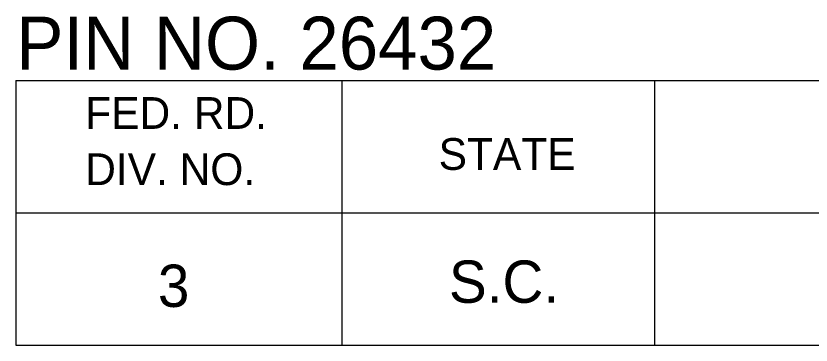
# Model space of a CAD drawing. Extents: x 1000 to 1162, y 999 to 8520.
# Drawn here: x 1133.06 to 1140.57, y 6160.05 to 6163.16 of the extents above; entities that cross this region are included whole.
import ezdxf

# ---------------------------------------------------------------- set-up
doc = ezdxf.new("R2010")
doc.units = 0
doc.layers.add('Level 20', color=7, linetype='Continuous')
doc.layers.add('Level 3', color=7, linetype='Continuous')

msp = doc.modelspace()

# ---------------------------------------------------------------- linework, layer by layer
at = {"layer": 'Level 3'}
for p, q in [((1133.055, 6162.5458), (1161.555, 6162.5458)), ((1133.055, 6162.5458), (1133.055, 6160.0458)), ((1133.055, 6162.5458), (1161.555, 6162.5458)), ((1133.055, 6162.5458), (1133.055, 6160.0458)), ((1133.055, 6162.5458), (1161.555, 6162.5458)), ((1133.055, 6162.5458), (1133.055, 6160.0458)), ((1133.055, 6162.5458), (1161.555, 6162.5458)), ((1133.055, 6162.5458), (1133.055, 6160.0458)), ((1133.055, 6162.5458), (1161.555, 6162.5458)), ((1133.055, 6162.5458), (1133.055, 6160.0458)), ((1133.055, 6162.5458), (1161.555, 6162.5458)), ((1133.055, 6162.5458), (1133.055, 6160.0458)), ((1133.055, 6162.5458), (1161.555, 6162.5458)), ((1133.055, 6162.5458), (1133.055, 6160.0458)), ((1133.055, 6162.5458), (1161.555, 6162.5458)), ((1133.055, 6162.5458), (1133.055, 6160.0458)), ((1133.055, 6162.5458), (1161.555, 6162.5458)), ((1133.055, 6162.5458), (1133.055, 6160.0458)), ((1133.055, 6162.5458), (1161.555, 6162.5458)), ((1133.055, 6162.5458), (1133.055, 6160.0458)), ((1133.055, 6162.5458), (1161.555, 6162.5458)), ((1133.055, 6162.5458), (1133.055, 6160.0458)), ((1133.055, 6162.5458), (1161.555, 6162.5458)), ((1133.055, 6162.5458), (1133.055, 6160.0458)), ((1133.055, 6162.5458), (1161.555, 6162.5458)), ((1133.055, 6162.5458), (1133.055, 6160.0458)), ((1133.055, 6162.5458), (1161.555, 6162.5458)), ((1133.055, 6162.5458), (1133.055, 6160.0458)), ((1133.055, 6162.5458), (1161.555, 6162.5458)), ((1133.055, 6162.5458), (1133.055, 6160.0458)), ((1133.055, 6162.5458), (1161.555, 6162.5458)), ((1133.055, 6162.5458), (1133.055, 6160.0458)), ((1133.055, 6162.5458), (1161.555, 6162.5458)), ((1133.055, 6162.5458), (1133.055, 6160.0458)), ((1133.055, 6162.5458), (1161.555, 6162.5458)), ((1133.055, 6162.5458), (1133.055, 6160.0458)), ((1133.055, 6162.5458), (1161.555, 6162.5458)), ((1133.055, 6162.5458), (1133.055, 6160.0458)), ((1133.055, 6162.5458), (1161.555, 6162.5458)), ((1133.055, 6162.5458), (1133.055, 6160.0458)), ((1133.055, 6162.5458), (1161.555, 6162.5458)), ((1133.055, 6162.5458), (1133.055, 6160.0458)), ((1133.055, 6162.5458), (1161.555, 6162.5458)), ((1133.055, 6162.5458), (1133.055, 6160.0458)), ((1133.055, 6162.5458), (1161.555, 6162.5458)), ((1133.055, 6162.5458), (1133.055, 6160.0458)), ((1133.055, 6162.5458), (1161.555, 6162.5458)), ((1133.055, 6162.5458), (1133.055, 6160.0458)), ((1133.055, 6162.5458), (1161.555, 6162.5458)), ((1133.055, 6162.5458), (1133.055, 6160.0458)), ((1133.055, 6162.5458), (1161.555, 6162.5458)), ((1133.055, 6162.5458), (1133.055, 6160.0458)), ((1133.055, 6162.5458), (1161.555, 6162.5458)), ((1133.055, 6162.5458), (1133.055, 6160.0458)), ((1133.055, 6162.5458), (1161.555, 6162.5458)), ((1133.055, 6162.5458), (1133.055, 6160.0458)), ((1133.055, 6162.5458), (1161.555, 6162.5458)), ((1133.055, 6162.5458), (1133.055, 6160.0458)), ((1133.055, 6162.5458), (1161.555, 6162.5458)), ((1133.055, 6162.5458), (1133.055, 6160.0458)), ((1133.055, 6162.5458), (1161.555, 6162.5458)), ((1133.055, 6162.5458), (1133.055, 6160.0458)), ((1133.055, 6162.5458), (1161.555, 6162.5458)), ((1133.055, 6162.5458), (1133.055, 6160.0458)), ((1133.055, 6162.5458), (1161.555, 6162.5458)), ((1133.055, 6162.5458), (1133.055, 6160.0458)), ((1133.055, 6162.5458), (1161.555, 6162.5458)), ((1133.055, 6162.5458), (1133.055, 6160.0458)), ((1133.055, 6162.5458), (1161.555, 6162.5458)), ((1133.055, 6162.5458), (1133.055, 6160.0458)), ((1133.055, 6162.5458), (1161.555, 6162.5458)), ((1133.055, 6162.5458), (1133.055, 6160.0458)), ((1133.055, 6162.5458), (1161.555, 6162.5458)), ((1133.055, 6162.5458), (1133.055, 6160.0458)), ((1133.055, 6162.5458), (1161.555, 6162.5458)), ((1133.055, 6162.5458), (1133.055, 6160.0458)), ((1133.055, 6162.5458), (1161.555, 6162.5458)), ((1133.055, 6162.5458), (1133.055, 6160.0458)), ((1133.055, 6162.5458), (1161.555, 6162.5458)), ((1133.055, 6162.5458), (1133.055, 6160.0458)), ((1133.055, 6162.5458), (1161.555, 6162.5458)), ((1133.055, 6162.5458), (1133.055, 6160.0458)), ((1133.055, 6162.5458), (1161.555, 6162.5458)), ((1133.055, 6162.5458), (1133.055, 6160.0458)), ((1133.055, 6162.5458), (1161.555, 6162.5458)), ((1133.055, 6162.5458), (1133.055, 6160.0458)), ((1136.1323, 6162.5458), (1136.1323, 6160.0458)), ((1136.1323, 6162.5458), (1136.1323, 6160.0458)), ((1136.1323, 6162.5458), (1136.1323, 6160.0458)), ((1136.1323, 6162.5458), (1136.1323, 6160.0458)), ((1136.1323, 6162.5458), (1136.1323, 6160.0458)), ((1136.1323, 6162.5458), (1136.1323, 6160.0458)), ((1136.1323, 6162.5458), (1136.1323, 6160.0458)), ((1136.1323, 6162.5458), (1136.1323, 6160.0458)), ((1136.1323, 6162.5458), (1136.1323, 6160.0458)), ((1136.1323, 6162.5458), (1136.1323, 6160.0458)), ((1136.1323, 6162.5458), (1136.1323, 6160.0458)), ((1136.1323, 6162.5458), (1136.1323, 6160.0458)), ((1136.1323, 6162.5458), (1136.1323, 6160.0458)), ((1136.1323, 6162.5458), (1136.1323, 6160.0458)), ((1136.1323, 6162.5458), (1136.1323, 6160.0458)), ((1136.1323, 6162.5458), (1136.1323, 6160.0458)), ((1136.1323, 6162.5458), (1136.1323, 6160.0458)), ((1136.1323, 6162.5458), (1136.1323, 6160.0458)), ((1136.1323, 6162.5458), (1136.1323, 6160.0458)), ((1136.1323, 6162.5458), (1136.1323, 6160.0458)), ((1136.1323, 6162.5458), (1136.1323, 6160.0458)), ((1136.1323, 6162.5458), (1136.1323, 6160.0458)), ((1136.1323, 6162.5458), (1136.1323, 6160.0458)), ((1136.1323, 6162.5458), (1136.1323, 6160.0458)), ((1136.1323, 6162.5458), (1136.1323, 6160.0458)), ((1136.1323, 6162.5458), (1136.1323, 6160.0458)), ((1136.1323, 6162.5458), (1136.1323, 6160.0458)), ((1136.1323, 6162.5458), (1136.1323, 6160.0458)), ((1136.1323, 6162.5458), (1136.1323, 6160.0458)), ((1136.1323, 6162.5458), (1136.1323, 6160.0458)), ((1136.1323, 6162.5458), (1136.1323, 6160.0458)), ((1136.1323, 6162.5458), (1136.1323, 6160.0458)), ((1136.1323, 6162.5458), (1136.1323, 6160.0458)), ((1136.1323, 6162.5458), (1136.1323, 6160.0458)), ((1136.1323, 6162.5458), (1136.1323, 6160.0458)), ((1136.1323, 6162.5458), (1136.1323, 6160.0458)), ((1136.1323, 6162.5458), (1136.1323, 6160.0458)), ((1136.1323, 6162.5458), (1136.1323, 6160.0458)), ((1136.1323, 6162.5458), (1136.1323, 6160.0458)), ((1136.1323, 6162.5458), (1136.1323, 6160.0458)), ((1136.1323, 6162.5458), (1136.1323, 6160.0458)), ((1136.1323, 6162.5458), (1136.1323, 6160.0458)), ((1136.1323, 6162.5458), (1136.1323, 6160.0458)), ((1139.0868, 6162.5458), (1139.0868, 6160.0458)), ((1139.0868, 6162.5458), (1139.0868, 6160.0458)), ((1139.0868, 6162.5458), (1139.0868, 6160.0458)), ((1139.0868, 6162.5458), (1139.0868, 6160.0458)), ((1139.0868, 6162.5458), (1139.0868, 6160.0458)), ((1139.0868, 6162.5458), (1139.0868, 6160.0458)), ((1139.0868, 6162.5458), (1139.0868, 6160.0458)), ((1139.0868, 6162.5458), (1139.0868, 6160.0458)), ((1139.0868, 6162.5458), (1139.0868, 6160.0458)), ((1139.0868, 6162.5458), (1139.0868, 6160.0458)), ((1139.0868, 6162.5458), (1139.0868, 6160.0458)), ((1139.0868, 6162.5458), (1139.0868, 6160.0458)), ((1139.0868, 6162.5458), (1139.0868, 6160.0458)), ((1139.0868, 6162.5458), (1139.0868, 6160.0458)), ((1139.0868, 6162.5458), (1139.0868, 6160.0458)), ((1139.0868, 6162.5458), (1139.0868, 6160.0458)), ((1139.0868, 6162.5458), (1139.0868, 6160.0458)), ((1139.0868, 6162.5458), (1139.0868, 6160.0458)), ((1139.0868, 6162.5458), (1139.0868, 6160.0458)), ((1139.0868, 6162.5458), (1139.0868, 6160.0458)), ((1139.0868, 6162.5458), (1139.0868, 6160.0458)), ((1139.0868, 6162.5458), (1139.0868, 6160.0458)), ((1139.0868, 6162.5458), (1139.0868, 6160.0458)), ((1139.0868, 6162.5458), (1139.0868, 6160.0458)), ((1139.0868, 6162.5458), (1139.0868, 6160.0458)), ((1139.0868, 6162.5458), (1139.0868, 6160.0458)), ((1139.0868, 6162.5458), (1139.0868, 6160.0458)), ((1139.0868, 6162.5458), (1139.0868, 6160.0458)), ((1139.0868, 6162.5458), (1139.0868, 6160.0458)), ((1139.0868, 6162.5458), (1139.0868, 6160.0458)), ((1139.0868, 6162.5458), (1139.0868, 6160.0458)), ((1139.0868, 6162.5458), (1139.0868, 6160.0458)), ((1139.0868, 6162.5458), (1139.0868, 6160.0458)), ((1139.0868, 6162.5458), (1139.0868, 6160.0458)), ((1139.0868, 6162.5458), (1139.0868, 6160.0458)), ((1139.0868, 6162.5458), (1139.0868, 6160.0458)), ((1139.0868, 6162.5458), (1139.0868, 6160.0458)), ((1139.0868, 6162.5458), (1139.0868, 6160.0458)), ((1139.0868, 6162.5458), (1139.0868, 6160.0458)), ((1139.0868, 6162.5458), (1139.0868, 6160.0458)), ((1139.0868, 6162.5458), (1139.0868, 6160.0458)), ((1139.0868, 6162.5458), (1139.0868, 6160.0458)), ((1139.0868, 6162.5458), (1139.0868, 6160.0458)), ((1133.055, 6161.2958), (1161.555, 6161.2958)), ((1133.055, 6161.2958), (1161.555, 6161.2958)), ((1133.055, 6161.2958), (1161.555, 6161.2958)), ((1133.055, 6161.2958), (1161.555, 6161.2958)), ((1133.055, 6161.2958), (1161.555, 6161.2958)), ((1133.055, 6161.2958), (1161.555, 6161.2958)), ((1133.055, 6161.2958), (1161.555, 6161.2958)), ((1133.055, 6161.2958), (1161.555, 6161.2958)), ((1133.055, 6161.2958), (1161.555, 6161.2958)), ((1133.055, 6161.2958), (1161.555, 6161.2958)), ((1133.055, 6161.2958), (1161.555, 6161.2958)), ((1133.055, 6161.2958), (1161.555, 6161.2958)), ((1133.055, 6161.2958), (1161.555, 6161.2958)), ((1133.055, 6161.2958), (1161.555, 6161.2958)), ((1133.055, 6161.2958), (1161.555, 6161.2958)), ((1133.055, 6161.2958), (1161.555, 6161.2958)), ((1133.055, 6161.2958), (1161.555, 6161.2958)), ((1133.055, 6161.2958), (1161.555, 6161.2958)), ((1133.055, 6161.2958), (1161.555, 6161.2958)), ((1133.055, 6161.2958), (1161.555, 6161.2958)), ((1133.055, 6161.2958), (1161.555, 6161.2958)), ((1133.055, 6161.2958), (1161.555, 6161.2958)), ((1133.055, 6161.2958), (1161.555, 6161.2958)), ((1133.055, 6161.2958), (1161.555, 6161.2958)), ((1133.055, 6161.2958), (1161.555, 6161.2958)), ((1133.055, 6161.2958), (1161.555, 6161.2958)), ((1133.055, 6161.2958), (1161.555, 6161.2958)), ((1133.055, 6161.2958), (1161.555, 6161.2958)), ((1133.055, 6161.2958), (1161.555, 6161.2958)), ((1133.055, 6161.2958), (1161.555, 6161.2958)), ((1133.055, 6161.2958), (1161.555, 6161.2958)), ((1133.055, 6161.2958), (1161.555, 6161.2958)), ((1133.055, 6161.2958), (1161.555, 6161.2958)), ((1133.055, 6161.2958), (1161.555, 6161.2958)), ((1133.055, 6161.2958), (1161.555, 6161.2958)), ((1133.055, 6161.2958), (1161.555, 6161.2958)), ((1133.055, 6161.2958), (1161.555, 6161.2958)), ((1133.055, 6161.2958), (1161.555, 6161.2958)), ((1133.055, 6161.2958), (1161.555, 6161.2958)), ((1133.055, 6161.2958), (1161.555, 6161.2958)), ((1133.055, 6161.2958), (1161.555, 6161.2958)), ((1133.055, 6161.2958), (1161.555, 6161.2958)), ((1133.055, 6161.2958), (1161.555, 6161.2958)), ((1133.055, 6160.0458), (1161.555, 6160.0458)), ((1133.055, 6160.0458), (1161.555, 6160.0458)), ((1133.055, 6160.0458), (1161.555, 6160.0458)), ((1133.055, 6160.0458), (1161.555, 6160.0458)), ((1133.055, 6160.0458), (1161.555, 6160.0458)), ((1133.055, 6160.0458), (1161.555, 6160.0458)), ((1133.055, 6160.0458), (1161.555, 6160.0458)), ((1133.055, 6160.0458), (1161.555, 6160.0458)), ((1133.055, 6160.0458), (1161.555, 6160.0458)), ((1133.055, 6160.0458), (1161.555, 6160.0458)), ((1133.055, 6160.0458), (1161.555, 6160.0458)), ((1133.055, 6160.0458), (1161.555, 6160.0458)), ((1133.055, 6160.0458), (1161.555, 6160.0458)), ((1133.055, 6160.0458), (1161.555, 6160.0458)), ((1133.055, 6160.0458), (1161.555, 6160.0458)), ((1133.055, 6160.0458), (1161.555, 6160.0458)), ((1133.055, 6160.0458), (1161.555, 6160.0458)), ((1133.055, 6160.0458), (1161.555, 6160.0458)), ((1133.055, 6160.0458), (1161.555, 6160.0458)), ((1133.055, 6160.0458), (1161.555, 6160.0458)), ((1133.055, 6160.0458), (1161.555, 6160.0458)), ((1133.055, 6160.0458), (1161.555, 6160.0458)), ((1133.055, 6160.0458), (1161.555, 6160.0458)), ((1133.055, 6160.0458), (1161.555, 6160.0458)), ((1133.055, 6160.0458), (1161.555, 6160.0458)), ((1133.055, 6160.0458), (1161.555, 6160.0458)), ((1133.055, 6160.0458), (1161.555, 6160.0458)), ((1133.055, 6160.0458), (1161.555, 6160.0458)), ((1133.055, 6160.0458), (1161.555, 6160.0458)), ((1133.055, 6160.0458), (1161.555, 6160.0458)), ((1133.055, 6160.0458), (1161.555, 6160.0458)), ((1133.055, 6160.0458), (1161.555, 6160.0458)), ((1133.055, 6160.0458), (1161.555, 6160.0458)), ((1133.055, 6160.0458), (1161.555, 6160.0458)), ((1133.055, 6160.0458), (1161.555, 6160.0458)), ((1133.055, 6160.0458), (1161.555, 6160.0458)), ((1133.055, 6160.0458), (1161.555, 6160.0458)), ((1133.055, 6160.0458), (1161.555, 6160.0458)), ((1133.055, 6160.0458), (1161.555, 6160.0458)), ((1133.055, 6160.0458), (1161.555, 6160.0458)), ((1133.055, 6160.0458), (1161.555, 6160.0458)), ((1133.055, 6160.0458), (1161.555, 6160.0458)), ((1133.055, 6160.0458), (1161.555, 6160.0458))]:
    msp.add_line(p, q, dxfattribs=at)

# ---------------------------------------------------------------- texts
at = {"layer": 'Level 20'}
msp.add_text('PIN NO. 26432', height=0.5, dxfattribs=at).set_placement((1133.0578, 6162.65))
at = {"layer": 'Level 3'}
for s, height, p in [('FED. RD.', 0.3, (1133.7098, 6162.0896)), ('FED. RD.', 0.3, (1133.7098, 6162.0896)), ('FED. RD.', 0.3, (1133.7098, 6162.0896)), ('FED. RD.', 0.3, (1133.7098, 6162.0896)), ('FED. RD.', 0.3, (1133.7098, 6162.0896)), ('FED. RD.', 0.3, (1133.7098, 6162.0896)), ('FED. RD.', 0.3, (1133.7098, 6162.0896)), ('FED. RD.', 0.3, (1133.7098, 6162.0896)), ('FED. RD.', 0.3, (1133.7098, 6162.0896)), ('FED. RD.', 0.3, (1133.7098, 6162.0896)), ('FED. RD.', 0.3, (1133.7098, 6162.0896)), ('FED. RD.', 0.3, (1133.7098, 6162.0896)), ('FED. RD.', 0.3, (1133.7098, 6162.0896)), ('FED. RD.', 0.3, (1133.7098, 6162.0896)), ('FED. RD.', 0.3, (1133.7098, 6162.0896)), ('FED. RD.', 0.3, (1133.7098, 6162.0896)), ('FED. RD.', 0.3, (1133.7098, 6162.0896)), ('FED. RD.', 0.3, (1133.7098, 6162.0896)), ('FED. RD.', 0.3, (1133.7098, 6162.0896)), ('FED. RD.', 0.3, (1133.7098, 6162.0896)), ('FED. RD.', 0.3, (1133.7098, 6162.0896)), ('FED. RD.', 0.3, (1133.7098, 6162.0896)), ('FED. RD.', 0.3, (1133.7098, 6162.0896)), ('FED. RD.', 0.3, (1133.7098, 6162.0896)), ('FED. RD.', 0.3, (1133.7098, 6162.0896)), ('FED. RD.', 0.3, (1133.7098, 6162.0896)), ('FED. RD.', 0.3, (1133.7098, 6162.0896)), ('FED. RD.', 0.3, (1133.7098, 6162.0896)), ('FED. RD.', 0.3, (1133.7098, 6162.0896)), ('FED. RD.', 0.3, (1133.7098, 6162.0896)), ('FED. RD.', 0.3, (1133.7098, 6162.0896)), ('FED. RD.', 0.3, (1133.7098, 6162.0896)), ('FED. RD.', 0.3, (1133.7098, 6162.0896)), ('FED. RD.', 0.3, (1133.7098, 6162.0896)), ('FED. RD.', 0.3, (1133.7098, 6162.0896)), ('FED. RD.', 0.3, (1133.7098, 6162.0896)), ('FED. RD.', 0.3, (1133.7098, 6162.0896)), ('FED. RD.', 0.3, (1133.7098, 6162.0896)), ('FED. RD.', 0.3, (1133.7098, 6162.0896)), ('FED. RD.', 0.3, (1133.7098, 6162.0896)), ('FED. RD.', 0.3, (1133.7098, 6162.0896)), ('FED. RD.', 0.3, (1133.7098, 6162.0896)), ('FED. RD.', 0.3, (1133.7098, 6162.0896)), ('STATE', 0.3, (1137.0478, 6161.7021)), ('STATE', 0.3, (1137.0478, 6161.7021)), ('STATE', 0.3, (1137.0478, 6161.7021)), ('STATE', 0.3, (1137.0478, 6161.7021)), ('STATE', 0.3, (1137.0478, 6161.7021)), ('STATE', 0.3, (1137.0478, 6161.7021)), ('STATE', 0.3, (1137.0478, 6161.7021)), ('STATE', 0.3, (1137.0478, 6161.7021)), ('STATE', 0.3, (1137.0478, 6161.7021)), ('STATE', 0.3, (1137.0478, 6161.7021)), ('STATE', 0.3, (1137.0478, 6161.7021)), ('STATE', 0.3, (1137.0478, 6161.7021)), ('STATE', 0.3, (1137.0478, 6161.7021)), ('STATE', 0.3, (1137.0478, 6161.7021)), ('STATE', 0.3, (1137.0478, 6161.7021)), ('STATE', 0.3, (1137.0478, 6161.7021)), ('STATE', 0.3, (1137.0478, 6161.7021)), ('STATE', 0.3, (1137.0478, 6161.7021)), ('STATE', 0.3, (1137.0478, 6161.7021)), ('STATE', 0.3, (1137.0478, 6161.7021)), ('STATE', 0.3, (1137.0478, 6161.7021)), ('STATE', 0.3, (1137.0478, 6161.7021)), ('STATE', 0.3, (1137.0478, 6161.7021)), ('STATE', 0.3, (1137.0478, 6161.7021)), ('STATE', 0.3, (1137.0478, 6161.7021)), ('STATE', 0.3, (1137.0478, 6161.7021)), ('STATE', 0.3, (1137.0478, 6161.7021)), ('STATE', 0.3, (1137.0478, 6161.7021)), ('STATE', 0.3, (1137.0478, 6161.7021)), ('STATE', 0.3, (1137.0478, 6161.7021)), ('STATE', 0.3, (1137.0478, 6161.7021)), ('STATE', 0.3, (1137.0478, 6161.7021)), ('STATE', 0.3, (1137.0478, 6161.7021)), ('STATE', 0.3, (1137.0478, 6161.7021)), ('STATE', 0.3, (1137.0478, 6161.7021)), ('STATE', 0.3, (1137.0478, 6161.7021)), ('STATE', 0.3, (1137.0478, 6161.7021)), ('STATE', 0.3, (1137.0478, 6161.7021)), ('STATE', 0.3, (1137.0478, 6161.7021)), ('STATE', 0.3, (1137.0478, 6161.7021)), ('STATE', 0.3, (1137.0478, 6161.7021)), ('STATE', 0.3, (1137.0478, 6161.7021)), ('STATE', 0.3, (1137.0478, 6161.7021)), ('DIV. NO.', 0.3, (1133.7098, 6161.5583)), ('DIV. NO.', 0.3, (1133.7098, 6161.5583)), ('DIV. NO.', 0.3, (1133.7098, 6161.5583)), ('DIV. NO.', 0.3, (1133.7098, 6161.5583)), ('DIV. NO.', 0.3, (1133.7098, 6161.5583)), ('DIV. NO.', 0.3, (1133.7098, 6161.5583)), ('DIV. NO.', 0.3, (1133.7098, 6161.5583)), ('DIV. NO.', 0.3, (1133.7098, 6161.5583)), ('DIV. NO.', 0.3, (1133.7098, 6161.5583)), ('DIV. NO.', 0.3, (1133.7098, 6161.5583)), ('DIV. NO.', 0.3, (1133.7098, 6161.5583)), ('DIV. NO.', 0.3, (1133.7098, 6161.5583)), ('DIV. NO.', 0.3, (1133.7098, 6161.5583)), ('DIV. NO.', 0.3, (1133.7098, 6161.5583)), ('DIV. NO.', 0.3, (1133.7098, 6161.5583)), ('DIV. NO.', 0.3, (1133.7098, 6161.5583)), ('DIV. NO.', 0.3, (1133.7098, 6161.5583)), ('DIV. NO.', 0.3, (1133.7098, 6161.5583)), ('DIV. NO.', 0.3, (1133.7098, 6161.5583)), ('DIV. NO.', 0.3, (1133.7098, 6161.5583)), ('DIV. NO.', 0.3, (1133.7098, 6161.5583)), ('DIV. NO.', 0.3, (1133.7098, 6161.5583)), ('DIV. NO.', 0.3, (1133.7098, 6161.5583)), ('DIV. NO.', 0.3, (1133.7098, 6161.5583)), ('DIV. NO.', 0.3, (1133.7098, 6161.5583)), ('DIV. NO.', 0.3, (1133.7098, 6161.5583)), ('DIV. NO.', 0.3, (1133.7098, 6161.5583)), ('DIV. NO.', 0.3, (1133.7098, 6161.5583)), ('DIV. NO.', 0.3, (1133.7098, 6161.5583)), ('DIV. NO.', 0.3, (1133.7098, 6161.5583)), ('DIV. NO.', 0.3, (1133.7098, 6161.5583)), ('DIV. NO.', 0.3, (1133.7098, 6161.5583)), ('DIV. NO.', 0.3, (1133.7098, 6161.5583)), ('DIV. NO.', 0.3, (1133.7098, 6161.5583)), ('DIV. NO.', 0.3, (1133.7098, 6161.5583)), ('DIV. NO.', 0.3, (1133.7098, 6161.5583)), ('DIV. NO.', 0.3, (1133.7098, 6161.5583)), ('DIV. NO.', 0.3, (1133.7098, 6161.5583)), ('DIV. NO.', 0.3, (1133.7098, 6161.5583)), ('DIV. NO.', 0.3, (1133.7098, 6161.5583)), ('DIV. NO.', 0.3, (1133.7098, 6161.5583)), ('DIV. NO.', 0.3, (1133.7098, 6161.5583)), ('DIV. NO.', 0.3, (1133.7098, 6161.5583)), ('S.C.', 0.39999, (1137.1448, 6160.4458)), ('S.C.', 0.39999, (1137.1448, 6160.4458)), ('S.C.', 0.39999, (1137.1448, 6160.4458)), ('S.C.', 0.39999, (1137.1448, 6160.4458)), ('S.C.', 0.39999, (1137.1448, 6160.4458)), ('S.C.', 0.39999, (1137.1448, 6160.4458)), ('S.C.', 0.39999, (1137.1448, 6160.4458)), ('S.C.', 0.39999, (1137.1448, 6160.4458)), ('S.C.', 0.39999, (1137.1448, 6160.4458)), ('S.C.', 0.39999, (1137.1448, 6160.4458)), ('S.C.', 0.39999, (1137.1448, 6160.4458)), ('S.C.', 0.39999, (1137.1448, 6160.4458)), ('S.C.', 0.39999, (1137.1448, 6160.4458)), ('S.C.', 0.39999, (1137.1448, 6160.4458)), ('S.C.', 0.39999, (1137.1448, 6160.4458)), ('S.C.', 0.39999, (1137.1448, 6160.4458)), ('S.C.', 0.39999, (1137.1448, 6160.4458)), ('S.C.', 0.39999, (1137.1448, 6160.4458)), ('S.C.', 0.39999, (1137.1448, 6160.4458)), ('S.C.', 0.39999, (1137.1448, 6160.4458)), ('S.C.', 0.39999, (1137.1448, 6160.4458)), ('S.C.', 0.39999, (1137.1448, 6160.4458)), ('S.C.', 0.39999, (1137.1448, 6160.4458)), ('S.C.', 0.39999, (1137.1448, 6160.4458)), ('S.C.', 0.39999, (1137.1448, 6160.4458)), ('S.C.', 0.39999, (1137.1448, 6160.4458)), ('S.C.', 0.39999, (1137.1448, 6160.4458)), ('S.C.', 0.39999, (1137.1448, 6160.4458)), ('S.C.', 0.39999, (1137.1448, 6160.4458)), ('S.C.', 0.39999, (1137.1448, 6160.4458)), ('S.C.', 0.39999, (1137.1448, 6160.4458)), ('S.C.', 0.39999, (1137.1448, 6160.4458)), ('S.C.', 0.39999, (1137.1448, 6160.4458)), ('S.C.', 0.39999, (1137.1448, 6160.4458)), ('S.C.', 0.39999, (1137.1448, 6160.4458)), ('S.C.', 0.39999, (1137.1448, 6160.4458)), ('S.C.', 0.39999, (1137.1448, 6160.4458)), ('S.C.', 0.39999, (1137.1448, 6160.4458)), ('S.C.', 0.39999, (1137.1448, 6160.4458)), ('S.C.', 0.39999, (1137.1448, 6160.4458)), ('S.C.', 0.39999, (1137.1448, 6160.4458)), ('S.C.', 0.39999, (1137.1448, 6160.4458)), ('S.C.', 0.39999, (1137.1448, 6160.4458)), ('3', 0.4, (1134.3961, 6160.4065)), ('3', 0.4, (1134.3961, 6160.4065)), ('3', 0.4, (1134.3961, 6160.4065)), ('3', 0.4, (1134.3961, 6160.4065)), ('3', 0.4, (1134.3961, 6160.4065)), ('3', 0.4, (1134.3961, 6160.4065)), ('3', 0.4, (1134.3961, 6160.4065)), ('3', 0.4, (1134.3961, 6160.4065)), ('3', 0.4, (1134.3961, 6160.4065)), ('3', 0.4, (1134.3961, 6160.4065)), ('3', 0.4, (1134.3961, 6160.4065)), ('3', 0.4, (1134.3961, 6160.4065)), ('3', 0.4, (1134.3961, 6160.4065)), ('3', 0.4, (1134.3961, 6160.4065)), ('3', 0.4, (1134.3961, 6160.4065)), ('3', 0.4, (1134.3961, 6160.4065)), ('3', 0.4, (1134.3961, 6160.4065)), ('3', 0.4, (1134.3961, 6160.4065)), ('3', 0.4, (1134.3961, 6160.4065)), ('3', 0.4, (1134.3961, 6160.4065)), ('3', 0.4, (1134.3961, 6160.4065)), ('3', 0.4, (1134.3961, 6160.4065)), ('3', 0.4, (1134.3961, 6160.4065)), ('3', 0.4, (1134.3961, 6160.4065)), ('3', 0.4, (1134.3961, 6160.4065)), ('3', 0.4, (1134.3961, 6160.4065)), ('3', 0.4, (1134.3961, 6160.4065)), ('3', 0.4, (1134.3961, 6160.4065)), ('3', 0.4, (1134.3961, 6160.4065)), ('3', 0.4, (1134.3961, 6160.4065)), ('3', 0.4, (1134.3961, 6160.4065)), ('3', 0.4, (1134.3961, 6160.4065)), ('3', 0.4, (1134.3961, 6160.4065)), ('3', 0.4, (1134.3961, 6160.4065)), ('3', 0.4, (1134.3961, 6160.4065)), ('3', 0.4, (1134.3961, 6160.4065)), ('3', 0.4, (1134.3961, 6160.4065)), ('3', 0.4, (1134.3961, 6160.4065)), ('3', 0.4, (1134.3961, 6160.4065)), ('3', 0.4, (1134.3961, 6160.4065)), ('3', 0.4, (1134.3961, 6160.4065)), ('3', 0.4, (1134.3961, 6160.4065)), ('3', 0.4, (1134.3961, 6160.4065))]:
    msp.add_text(s, height=height, dxfattribs=at).set_placement(p)

doc.saveas('drawing.dxf')
